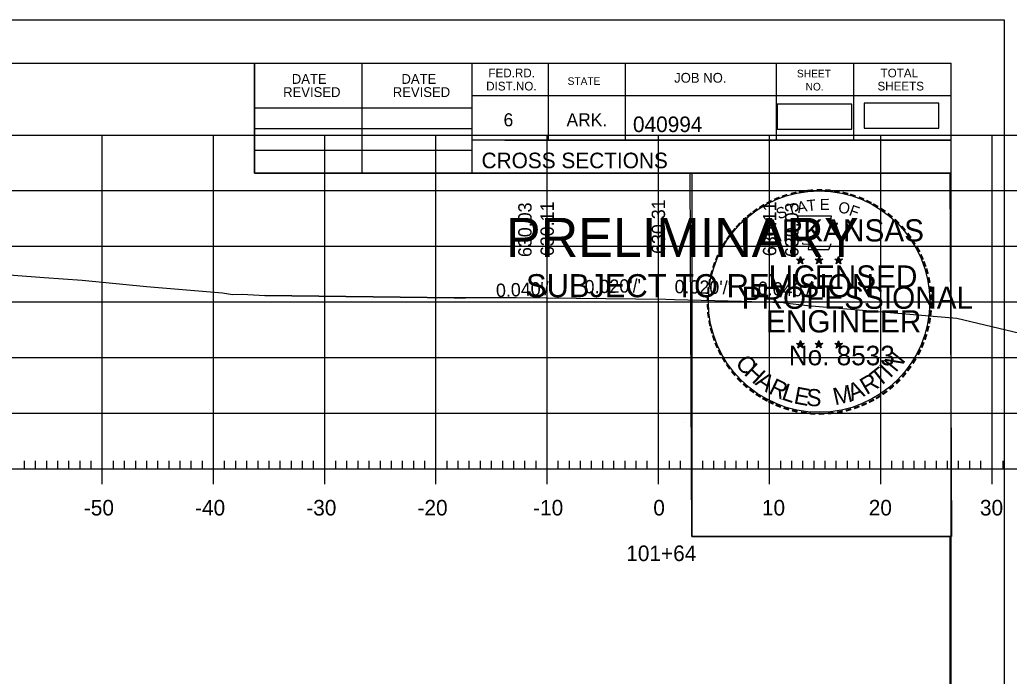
# Model space of a CAD drawing. Extents: x 1381471 to 1382703, y 370300 to 371487.
# Drawn here: x 1382079.2 to 1382168.2, y 370488.6 to 370547.6 of the extents above; entities that cross this region are included whole.
import ezdxf

# ---------------------------------------------------------------- set-up
doc = ezdxf.new("R2010")
doc.units = 0
for name, color, linetype in [('Level 26', 7, 'Continuous'), ('Level 45', 7, 'Continuous'), ('Level 6', 7, 'Continuous'), ('Level 8', 7, 'Continuous'), ('Level 9', 7, 'Continuous')]:
    doc.layers.add(name, color=color, linetype=linetype)

msp = doc.modelspace()

# ---------------------------------------------------------------- linework, layer by layer
at = {"layer": 'Level 26'}
for p, q in [((1381834.371, 370547.628), (1382167.705, 370547.628)), ((1382138.986, 370511.397), (1382138.986, 370511.397))]:
    msp.add_line(p, q, dxfattribs=at)
for points in [[(1381834.365, 370547.628), (1382167.705, 370547.628), (1382167.705, 370334.29), (1381834.365, 370334.29)], [(1382080.692, 370543.733), (1382100.312, 370543.733), (1382100.312, 370533.853), (1382116.424, 370533.853), (1382139.624, 370533.853), (1382139.624, 370501.183), (1382162.831, 370501.183), (1382162.952, 370338.273), (1381846.772, 370338.273), (1381846.772, 370543.733)], [(1382139.484, 370533.853), (1382162.831, 370533.853), (1382162.972, 370501.183), (1382139.624, 370501.183)]]:
    msp.add_lwpolyline(points, close=True, dxfattribs=at)
msp.add_circle((1382151.064, 370522.293), 9.952, dxfattribs=at)
at = {"layer": 'Level 45'}
for p, q in [((1381996.613, 370537.267), (1382276.613, 370537.267)), ((1382086.613, 370507.267), (1382086.613, 370537.267)), ((1382096.613, 370507.267), (1382096.613, 370537.267)), ((1382106.613, 370507.267), (1382106.613, 370537.267)), ((1382116.613, 370507.267), (1382116.613, 370537.267)), ((1382126.613, 370507.267), (1382126.613, 370537.267)), ((1382136.613, 370507.267), (1382136.613, 370537.267)), ((1382146.613, 370507.267), (1382146.613, 370537.267)), ((1382156.613, 370507.267), (1382156.613, 370537.267)), ((1382166.613, 370507.267), (1382166.613, 370537.267)), ((1381996.613, 370532.267), (1382276.613, 370532.267)), ((1381996.613, 370527.267), (1382276.613, 370527.267)), ((1381996.613, 370522.267), (1382276.613, 370522.267)), ((1382118.241, 370522.631), (1382101.218, 370522.852)), ((1381996.613, 370517.267), (1382276.613, 370517.267)), ((1381996.613, 370512.267), (1382276.613, 370512.267)), ((1382086.613, 370505.867), (1382086.613, 370508.667)), ((1382096.613, 370505.867), (1382096.613, 370508.667)), ((1382106.613, 370505.867), (1382106.613, 370508.667)), ((1382116.613, 370505.867), (1382116.613, 370508.667)), ((1382126.613, 370505.867), (1382126.613, 370508.667)), ((1382136.613, 370505.867), (1382136.613, 370508.667)), ((1382146.613, 370505.867), (1382146.613, 370508.667)), ((1382156.613, 370505.867), (1382156.613, 370508.667)), ((1382166.613, 370505.867), (1382166.613, 370508.667)), ((1381996.613, 370507.267), (1382276.613, 370507.267)), ((1381996.613, 370507.267), (1382276.613, 370507.267)), ((1382079.613, 370507.267), (1382079.613, 370507.967)), ((1382080.613, 370507.267), (1382080.613, 370507.967)), ((1382081.613, 370507.267), (1382081.613, 370507.967)), ((1382082.613, 370507.267), (1382082.613, 370507.967)), ((1382083.613, 370507.267), (1382083.613, 370507.967)), ((1382084.613, 370507.267), (1382084.613, 370507.967)), ((1382085.613, 370507.267), (1382085.613, 370507.967)), ((1382087.613, 370507.267), (1382087.613, 370507.967)), ((1382088.613, 370507.267), (1382088.613, 370507.967)), ((1382089.613, 370507.267), (1382089.613, 370507.967)), ((1382090.613, 370507.267), (1382090.613, 370507.967)), ((1382091.613, 370507.267), (1382091.613, 370507.967)), ((1382092.613, 370507.267), (1382092.613, 370507.967)), ((1382093.613, 370507.267), (1382093.613, 370507.967)), ((1382094.613, 370507.267), (1382094.613, 370507.967)), ((1382095.613, 370507.267), (1382095.613, 370507.967)), ((1382097.613, 370507.267), (1382097.613, 370507.967)), ((1382098.613, 370507.267), (1382098.613, 370507.967)), ((1382099.613, 370507.267), (1382099.613, 370507.967)), ((1382100.613, 370507.267), (1382100.613, 370507.967)), ((1382101.613, 370507.267), (1382101.613, 370507.967)), ((1382102.613, 370507.267), (1382102.613, 370507.967)), ((1382103.613, 370507.267), (1382103.613, 370507.967)), ((1382104.613, 370507.267), (1382104.613, 370507.967)), ((1382105.613, 370507.267), (1382105.613, 370507.967)), ((1382107.613, 370507.267), (1382107.613, 370507.967)), ((1382108.613, 370507.267), (1382108.613, 370507.967)), ((1382109.613, 370507.267), (1382109.613, 370507.967)), ((1382110.613, 370507.267), (1382110.613, 370507.967)), ((1382111.613, 370507.267), (1382111.613, 370507.967)), ((1382112.613, 370507.267), (1382112.613, 370507.967)), ((1382113.613, 370507.267), (1382113.613, 370507.967)), ((1382114.613, 370507.267), (1382114.613, 370507.967)), ((1382115.613, 370507.267), (1382115.613, 370507.967)), ((1382117.613, 370507.267), (1382117.613, 370507.967)), ((1382118.613, 370507.267), (1382118.613, 370507.967)), ((1382119.613, 370507.267), (1382119.613, 370507.967)), ((1382120.613, 370507.267), (1382120.613, 370507.967)), ((1382121.613, 370507.267), (1382121.613, 370507.967)), ((1382122.613, 370507.267), (1382122.613, 370507.967)), ((1382123.613, 370507.267), (1382123.613, 370507.967)), ((1382124.613, 370507.267), (1382124.613, 370507.967)), ((1382125.613, 370507.267), (1382125.613, 370507.967)), ((1382127.613, 370507.267), (1382127.613, 370507.967)), ((1382128.613, 370507.267), (1382128.613, 370507.967)), ((1382129.613, 370507.267), (1382129.613, 370507.967)), ((1382130.613, 370507.267), (1382130.613, 370507.967)), ((1382131.613, 370507.267), (1382131.613, 370507.967)), ((1382132.613, 370507.267), (1382132.613, 370507.967)), ((1382133.613, 370507.267), (1382133.613, 370507.967)), ((1382134.613, 370507.267), (1382134.613, 370507.967)), ((1382135.613, 370507.267), (1382135.613, 370507.967)), ((1382137.613, 370507.267), (1382137.613, 370507.967)), ((1382138.613, 370507.267), (1382138.613, 370507.967)), ((1382139.613, 370507.267), (1382139.613, 370507.967)), ((1382140.613, 370507.267), (1382140.613, 370507.967)), ((1382141.613, 370507.267), (1382141.613, 370507.967)), ((1382142.613, 370507.267), (1382142.613, 370507.967)), ((1382143.613, 370507.267), (1382143.613, 370507.967)), ((1382144.613, 370507.267), (1382144.613, 370507.967)), ((1382145.613, 370507.267), (1382145.613, 370507.967)), ((1382147.613, 370507.267), (1382147.613, 370507.967)), ((1382148.613, 370507.267), (1382148.613, 370507.967)), ((1382149.613, 370507.267), (1382149.613, 370507.967)), ((1382150.613, 370507.267), (1382150.613, 370507.967)), ((1382151.613, 370507.267), (1382151.613, 370507.967)), ((1382152.613, 370507.267), (1382152.613, 370507.967)), ((1382153.613, 370507.267), (1382153.613, 370507.967)), ((1382154.613, 370507.267), (1382154.613, 370507.967)), ((1382155.613, 370507.267), (1382155.613, 370507.967)), ((1382157.613, 370507.267), (1382157.613, 370507.967)), ((1382158.613, 370507.267), (1382158.613, 370507.967)), ((1382159.613, 370507.267), (1382159.613, 370507.967)), ((1382160.613, 370507.267), (1382160.613, 370507.967)), ((1382161.613, 370507.267), (1382161.613, 370507.967)), ((1382162.613, 370507.267), (1382162.613, 370507.967)), ((1382163.613, 370507.267), (1382163.613, 370507.967)), ((1382164.613, 370507.267), (1382164.613, 370507.967)), ((1382165.613, 370507.267), (1382165.613, 370507.967)), ((1382167.613, 370507.267), (1382167.613, 370507.967))]:
    msp.add_line(p, q, dxfattribs=at)
for points in [[(1382070.712, 370525.284), (1382081.391, 370524.455), (1382084.791, 370524.226), (1382090.588, 370523.658), (1382097.41, 370523.091), (1382098.331, 370522.938), (1382099.201, 370522.951), (1382101.218, 370522.852), (1382118.241, 370522.631), (1382118.948, 370522.63), (1382119.266, 370522.623), (1382123.374, 370522.676), (1382123.825, 370522.668), (1382137.286, 370522.508), (1382138.076, 370522.487), (1382144.074, 370522.318), (1382147.845, 370522.211), (1382147.877, 370522.205), (1382147.953, 370522.197), (1382150.033, 370521.941), (1382163.451, 370520.799), (1382171.626, 370518.866)], [(1382123.825, 370522.668), (1382119.266, 370522.623), (1382118.241, 370522.631)]]:
    msp.add_lwpolyline(points, dxfattribs=at)
at = {"layer": 'Level 6'}
for p, q in [((1381846.772, 370543.733), (1382162.952, 370543.733)), ((1382100.312, 370533.853), (1382100.312, 370543.733)), ((1382109.992, 370533.853), (1382109.992, 370543.733)), ((1382119.852, 370543.733), (1382119.852, 370533.853)), ((1382126.692, 370543.733), (1382126.692, 370536.793)), ((1382133.632, 370543.733), (1382133.632, 370536.793)), ((1382147.212, 370543.733), (1382147.212, 370536.793)), ((1382154.152, 370543.733), (1382154.152, 370536.793)), ((1382162.952, 370338.273), (1382162.952, 370543.733)), ((1382162.952, 370540.793), (1382119.852, 370540.793)), ((1382162.952, 370540.813), (1382162.952, 370540.813)), ((1382100.312, 370539.713), (1382119.852, 370539.713)), ((1382100.312, 370537.853), (1382119.852, 370537.853)), ((1382162.952, 370536.793), (1382119.852, 370536.793)), ((1382122.812, 370536.793), (1382162.952, 370536.793)), ((1382100.312, 370535.913), (1382119.852, 370535.913)), ((1382162.952, 370533.853), (1382100.312, 370533.853))]:
    msp.add_line(p, q, dxfattribs=at)
for points in [[(1382147.299, 370537.804), (1382154.01, 370537.804), (1382154.01, 370540.041), (1382147.299, 370540.041)], [(1382155.106, 370537.896), (1382161.817, 370537.896), (1382161.817, 370540.133), (1382155.106, 370540.133)]]:
    msp.add_lwpolyline(points, close=True, dxfattribs=at)
at = {"layer": 'Level 8'}
for p, q in [((1382149.037, 370526.108), (1382149.386, 370525.997)), ((1382149.037, 370526.108), (1382149.29, 370526.063)), ((1382149.037, 370526.108), (1382149.274, 370525.986)), ((1382149.17, 370525.7), (1382149.386, 370525.997)), ((1382149.17, 370525.7), (1382149.296, 370525.944)), ((1382149.17, 370525.7), (1382149.384, 370525.917)), ((1382149.386, 370526.362), (1382149.345, 370526.11)), ((1382149.599, 370525.7), (1382149.384, 370525.914)), ((1382149.386, 370525.997), (1382149.386, 370526.362)), ((1382149.386, 370526.362), (1382149.435, 370526.112)), ((1382149.733, 370526.108), (1382149.386, 370525.997)), ((1382149.599, 370525.7), (1382149.386, 370525.997)), ((1382149.733, 370526.108), (1382149.447, 370526.059)), ((1382149.599, 370525.7), (1382149.462, 370525.991)), ((1382149.733, 370526.108), (1382149.529, 370526.006)), ((1382150.707, 370526.108), (1382151.056, 370525.997)), ((1382150.707, 370526.108), (1382150.96, 370526.063)), ((1382150.707, 370526.108), (1382150.944, 370525.986)), ((1382150.84, 370525.7), (1382151.056, 370525.997)), ((1382150.84, 370525.7), (1382150.966, 370525.944)), ((1382150.84, 370525.7), (1382151.054, 370525.917)), ((1382151.056, 370526.362), (1382151.015, 370526.11)), ((1382151.269, 370525.7), (1382151.054, 370525.914)), ((1382151.056, 370525.997), (1382151.056, 370526.362)), ((1382151.056, 370526.362), (1382151.105, 370526.112)), ((1382151.403, 370526.108), (1382151.056, 370525.997)), ((1382151.269, 370525.7), (1382151.056, 370525.997)), ((1382151.403, 370526.108), (1382151.117, 370526.059)), ((1382151.269, 370525.7), (1382151.132, 370525.991)), ((1382151.403, 370526.108), (1382151.199, 370526.006)), ((1382152.471, 370526.096), (1382152.82, 370525.985)), ((1382152.471, 370526.096), (1382152.724, 370526.051)), ((1382152.471, 370526.096), (1382152.708, 370525.974)), ((1382152.604, 370525.688), (1382152.82, 370525.985)), ((1382152.604, 370525.688), (1382152.73, 370525.932)), ((1382152.604, 370525.688), (1382152.818, 370525.905)), ((1382152.82, 370526.35), (1382152.779, 370526.098)), ((1382153.033, 370525.688), (1382152.818, 370525.902)), ((1382152.82, 370525.985), (1382152.82, 370526.35)), ((1382152.82, 370526.35), (1382152.869, 370526.1)), ((1382153.167, 370526.096), (1382152.82, 370525.985)), ((1382153.033, 370525.688), (1382152.82, 370525.985)), ((1382153.167, 370526.096), (1382152.881, 370526.047)), ((1382153.033, 370525.688), (1382152.896, 370525.979)), ((1382153.167, 370526.096), (1382152.963, 370525.994)), ((1382149.382, 370518.789), (1382149.341, 370518.537)), ((1382149.382, 370518.424), (1382149.382, 370518.789)), ((1382149.382, 370518.789), (1382149.431, 370518.539)), ((1382151.051, 370518.789), (1382151.01, 370518.537)), ((1382151.051, 370518.424), (1382151.051, 370518.789)), ((1382151.051, 370518.789), (1382151.1, 370518.539)), ((1382152.818, 370518.779), (1382152.777, 370518.527)), ((1382152.818, 370518.414), (1382152.818, 370518.779)), ((1382152.818, 370518.779), (1382152.867, 370518.529)), ((1382149.033, 370518.535), (1382149.382, 370518.424)), ((1382149.033, 370518.535), (1382149.286, 370518.49)), ((1382149.033, 370518.535), (1382149.27, 370518.413)), ((1382149.166, 370518.127), (1382149.382, 370518.424)), ((1382149.166, 370518.127), (1382149.292, 370518.371)), ((1382149.166, 370518.127), (1382149.38, 370518.344)), ((1382149.595, 370518.127), (1382149.38, 370518.341)), ((1382149.729, 370518.535), (1382149.382, 370518.424)), ((1382149.595, 370518.127), (1382149.382, 370518.424)), ((1382149.729, 370518.535), (1382149.443, 370518.486)), ((1382149.595, 370518.127), (1382149.458, 370518.418)), ((1382149.729, 370518.535), (1382149.525, 370518.433)), ((1382150.702, 370518.535), (1382151.051, 370518.424)), ((1382150.702, 370518.535), (1382150.955, 370518.49)), ((1382150.702, 370518.535), (1382150.939, 370518.413)), ((1382150.835, 370518.127), (1382151.051, 370518.424)), ((1382150.835, 370518.127), (1382150.961, 370518.371)), ((1382150.835, 370518.127), (1382151.049, 370518.344)), ((1382151.264, 370518.127), (1382151.049, 370518.341)), ((1382151.398, 370518.535), (1382151.051, 370518.424)), ((1382151.264, 370518.127), (1382151.051, 370518.424)), ((1382151.398, 370518.535), (1382151.112, 370518.486)), ((1382151.264, 370518.127), (1382151.127, 370518.418)), ((1382151.398, 370518.535), (1382151.194, 370518.433)), ((1382152.469, 370518.525), (1382152.818, 370518.414)), ((1382152.469, 370518.525), (1382152.722, 370518.48)), ((1382152.469, 370518.525), (1382152.706, 370518.403)), ((1382152.602, 370518.117), (1382152.818, 370518.414)), ((1382152.602, 370518.117), (1382152.728, 370518.361)), ((1382152.602, 370518.117), (1382152.816, 370518.334)), ((1382153.031, 370518.117), (1382152.816, 370518.331)), ((1382153.165, 370518.525), (1382152.818, 370518.414)), ((1382153.031, 370518.117), (1382152.818, 370518.414)), ((1382153.165, 370518.525), (1382152.879, 370518.476)), ((1382153.031, 370518.117), (1382152.894, 370518.408)), ((1382153.165, 370518.525), (1382152.961, 370518.423))]:
    msp.add_line(p, q, dxfattribs=at)
for points in [[(1382149.078, 370529.986), (1382149.347, 370529.159)], [(1382152.589, 370529.064), (1382152.731, 370529.348), (1382152.046, 370529.324), (1382152.194, 370529.986), (1382149.078, 370529.986)], [(1382149.57, 370527.563), (1382149.57, 370527.476), (1382150.133, 370527.457), (1382150.079, 370526.984), (1382151.949, 370526.984), (1382152.15, 370527.52)], [(1382149.386, 370526.362), (1382149.599, 370525.7), (1382149.037, 370526.108), (1382149.733, 370526.108), (1382149.17, 370525.7), (1382149.386, 370526.362)], [(1382151.056, 370526.362), (1382151.269, 370525.7), (1382150.707, 370526.108), (1382151.403, 370526.108), (1382150.84, 370525.7), (1382151.056, 370526.362)], [(1382152.82, 370526.35), (1382153.033, 370525.688), (1382152.471, 370526.096), (1382153.167, 370526.096), (1382152.604, 370525.688), (1382152.82, 370526.35)], [(1382149.382, 370518.789), (1382149.595, 370518.127), (1382149.033, 370518.535), (1382149.729, 370518.535), (1382149.166, 370518.127), (1382149.382, 370518.789)], [(1382151.051, 370518.789), (1382151.264, 370518.127), (1382150.702, 370518.535), (1382151.398, 370518.535), (1382150.835, 370518.127), (1382151.051, 370518.789)], [(1382152.818, 370518.779), (1382153.031, 370518.117), (1382152.469, 370518.525), (1382153.165, 370518.525), (1382152.602, 370518.117), (1382152.818, 370518.779)]]:
    msp.add_lwpolyline(points, dxfattribs=at)
for centre, radius in [((1382149.385, 370525.996), 0.172), ((1382149.385, 370525.996), 0.145), ((1382149.385, 370525.996), 0.116), ((1382149.385, 370525.996), 0.0991), ((1382149.385, 370525.996), 0.0747), ((1382149.385, 370525.996), 0.0495), ((1382149.385, 370525.996), 0.0296), ((1382151.055, 370525.996), 0.172), ((1382151.055, 370525.996), 0.145), ((1382151.055, 370525.996), 0.116), ((1382151.055, 370525.996), 0.0991), ((1382151.055, 370525.996), 0.0747), ((1382151.055, 370525.996), 0.0495), ((1382151.055, 370525.996), 0.0296), ((1382152.819, 370525.984), 0.172), ((1382152.819, 370525.984), 0.145), ((1382152.819, 370525.984), 0.116), ((1382152.819, 370525.984), 0.0991), ((1382152.819, 370525.984), 0.0747), ((1382152.819, 370525.984), 0.0495), ((1382152.819, 370525.984), 0.0296), ((1382149.381, 370518.423), 0.172), ((1382149.381, 370518.423), 0.145), ((1382149.381, 370518.423), 0.116), ((1382149.381, 370518.423), 0.0991), ((1382149.381, 370518.423), 0.0747), ((1382149.381, 370518.423), 0.0495), ((1382149.381, 370518.423), 0.0296), ((1382151.05, 370518.423), 0.172), ((1382151.05, 370518.423), 0.145), ((1382151.05, 370518.423), 0.116), ((1382151.05, 370518.423), 0.0991), ((1382151.05, 370518.423), 0.0747), ((1382151.05, 370518.423), 0.0495), ((1382151.05, 370518.423), 0.0296), ((1382152.817, 370518.413), 0.172), ((1382152.817, 370518.413), 0.145), ((1382152.817, 370518.413), 0.116), ((1382152.817, 370518.413), 0.0991), ((1382152.817, 370518.413), 0.0747), ((1382152.817, 370518.413), 0.0495), ((1382152.817, 370518.413), 0.0296)]:
    msp.add_circle(centre, radius, dxfattribs=at)

# ---------------------------------------------------------------- texts
at = {"layer": 'Level 45'}
for s, rotation, p in [('630.03', 90, (1382125.213, 370526.297)), ('630.11', 90, (1382127.213, 370526.377)), ('630.31', 90, (1382137.213, 370526.577)), ('630.11', 90, (1382147.213, 370526.377)), ('630.03', 90, (1382149.213, 370526.297)), ("0.040'/'", 2.29061, (1382122.034, 370522.694)), ("0.020'/'", 1.14576, (1382129.989, 370523.027)), ("0.020'/'", 358.85424, (1382138.062, 370523.048)), ("0.040'/'", 357.70939, (1382145.536, 370522.909))]:
    msp.add_text(s, height=1.2, rotation=rotation, dxfattribs=at).set_placement(p)
for s, p in [('-50', (1382084.954, 370503.067)), ('-40', (1382094.954, 370503.067)), ('-30', (1382104.954, 370503.067)), ('-20', (1382114.954, 370503.067)), ('-10', (1382125.351, 370503.067)), ('0', (1382136.156, 370503.067)), ('10', (1382145.924, 370503.067)), ('20', (1382155.528, 370503.067)), ('30', (1382165.528, 370503.067)), ('101+64', (1382133.725, 370498.967))]:
    msp.add_text(s, height=1.4, dxfattribs=at).set_placement(p)
at = {"layer": 'Level 6'}
for s, height, p in [('DATE', 0.8792, (1382103.65, 370541.869)), ('DATE', 0.8792, (1382113.51, 370541.869)), ('FED.RD.', 0.7819, (1382121.332, 370542.453)), ('JOB NO.', 0.8792, (1382138.032, 370541.973)), ('SHEET', 0.684, (1382149.072, 370542.453)), ('TOTAL', 0.7819, (1382156.592, 370542.453)), ('DIST.NO.', 0.7819, (1382121.132, 370541.273)), ('STATE', 0.684, (1382128.452, 370541.773)), ('NO.', 0.684, (1382149.852, 370541.273)), ('SHEETS', 0.7819, (1382156.312, 370541.273)), ('REVISED', 0.8792, (1382102.87, 370540.689)), ('REVISED', 0.8792, (1382112.73, 370540.689)), ('6', 1.172, (1382122.692, 370538.053)), ('ARK.', 1.1723, (1382128.352, 370538.053)), ('040994', 1.4, (1382134.328, 370537.532)), ('CROSS SECTIONS', 1.4, (1382120.716, 370534.283))]:
    msp.add_text(s, height=height, rotation=360, dxfattribs=at).set_placement(p)
at = {"layer": 'Level 8'}
for s, height, rotation, p in [('-', 1.6, 13.63015, (1382148.576, 370531.354)), ('-', 1.6, 10.21935, (1382149.254, 370531.516)), ('-', 1.6, 5.89682, (1382149.983, 370531.626)), ('-', 1.6, 0.18623, (1382150.755, 370531.698)), ('-', 1.6, 357.74304, (1382151.478, 370531.685)), ('-', 1.6, 352.16172, (1382152.222, 370531.629)), ('-', 1.6, 347.20489, (1382152.941, 370531.515)), ('-', 1.6, 342.3362, (1382153.576, 370531.36)), ('-', 1.6, 28.79182, (1382146.559, 370530.527)), ('-', 1.6, 24.30721, (1382147.192, 370530.844)), ('-', 1.6, 19.17608, (1382147.826, 370531.113)), ('T', 1, 16.4036, (1382148.347, 370529.995)), ('A', 1, 11.21318, (1382149.173, 370530.246)), ('T', 1, 6.02276, (1382150.022, 370530.412)), ('E', 1, 0.83234, (1382151.127, 370530.522)), ('O', 1, 350.4515, (1382152.731, 370530.312)), ('-', 1.6, 337.85509, (1382154.311, 370531.137)), ('-', 1.6, 334.12109, (1382154.942, 370530.866)), ('-', 1.6, 329.64089, (1382155.521, 370530.583)), ('-', 1.6, 38.95066, (1382144.908, 370529.384)), ('-', 1.6, 36.23174, (1382145.384, 370529.762)), ('-', 1.6, 34.06357, (1382145.962, 370530.157)), ('S', 1, 21.59401, (1382147.433, 370529.664)), ('F', 1, 340.07066, (1382153.685, 370530.084)), ('-', 1.6, 325.86266, (1382156.164, 370530.222)), ('-', 1.6, 320.52971, (1382156.774, 370529.796)), ('-', 1.6, 48.42305, (1382144.027, 370528.489)), ('-', 1.6, 42.96224, (1382144.475, 370528.967)), ('ARKANSAS', 2, 360, (1382145.931, 370527.698)), ('-', 1.6, 315.57859, (1382157.373, 370529.308)), ('-', 1.6, 50.61417, (1382143.624, 370528.003)), ('-', 1.6, 309.87973, (1382157.942, 370528.758)), ('-', 1.6, 306.65218, (1382158.467, 370528.156)), ('-', 1.6, 58.07063, (1382142.886, 370526.909)), ('-', 1.6, 54.23247, (1382143.211, 370527.436)), ('-', 1.4, 303.67529, (1382158.953, 370527.588)), ('-', 1.6, 62.87135, (1382142.573, 370526.295)), ('-', 1.6, 299.66835, (1382159.272, 370526.981)), ('-', 1.6, 72.39447, (1382142.095, 370525.054)), ('-', 1.6, 67.77427, (1382142.314, 370525.684)), ('DWB', 0.01, 360, (1382149.373, 370525.992)), ('DWB', 0.01, 360, (1382151.043, 370525.992)), ('DWB', 0.01, 360, (1382152.807, 370525.981)), ('-', 1.6, 294.66279, (1382159.596, 370526.369)), ('-', 1.6, 290.57283, (1382159.853, 370525.792)), ('-', 1.6, 75.46096, (1382141.898, 370524.34)), ('LICENSED', 2, 360, (1382146.528, 370523.549)), ('-', 1.6, 285.12326, (1382160.087, 370525.212)), ('-', 1.6, 81.20126, (1382141.766, 370523.627)), ('-', 1.6, 280.54934, (1382160.287, 370524.47)), ('-', 1.6, 85.18634, (1382141.69, 370522.936)), ('PROFESSIONAL', 2, 360, (1382144.105, 370521.645)), ('-', 1.6, 276.59616, (1382160.449, 370523.702)), ('-', 1.6, 89.06224, (1382141.665, 370522.235)), ('-', 1.6, 274.33011, (1382160.509, 370522.98)), ('-', 1.6, 269.94067, (1382160.543, 370522.348)), ('-', 1.6, 94.19588, (1382141.7, 370521.51)), ('-', 1.6, 98.94793, (1382141.772, 370520.843)), ('ENGINEER', 2, 360, (1382146.292, 370519.52)), ('-', 1.6, 263.5172, (1382160.524, 370521.682)), ('-', 1.6, 101.71495, (1382141.907, 370520.11)), ('-', 1.6, 260.99529, (1382160.453, 370521.028)), ('-', 1.6, 105.45785, (1382142.069, 370519.515)), ('-', 1.6, 255.7626, (1382160.343, 370520.35)), ('-', 1.6, 109.08742, (1382142.284, 370518.884)), ('-', 1.6, 247.88866, (1382159.939, 370518.957)), ('-', 1.6, 252.86809, (1382160.162, 370519.63)), ('-', 1.6, 114.06432, (1382142.538, 370518.288)), ('-', 1.6, 115.72885, (1382142.843, 370517.67)), ('No. 8533', 1.757, 360, (1382148.334, 370516.569)), ('DWB', 0.01, 360, (1382149.369, 370518.419)), ('DWB', 0.01, 360, (1382151.038, 370518.419)), ('DWB', 0.01, 360, (1382152.805, 370518.409)), ('N', 1.54, 50.78344, (1382157.971, 370515.868)), ('-', 1.6, 244.61971, (1382159.677, 370518.328)), ('-', 1.6, 120.44712, (1382143.2, 370517.084)), ('C', 1.54, 309.95483, (1382143.456, 370516.716)), ('-', 1.6, 239.07125, (1382159.283, 370517.576)), ('-', 1.6, 125.89344, (1382143.603, 370516.523)), ('-', 1.6, 130.71812, (1382144.065, 370515.971)), ('H', 1.54, 317.38726, (1382144.242, 370515.778)), ('T', 1.54, 38.42805, (1382156.437, 370514.539)), ('I', 1.54, 46.30332, (1382157.448, 370515.348)), ('-', 1.6, 233.84524, (1382158.881, 370516.923)), ('-', 1.6, 134.22381, (1382144.582, 370515.426)), ('A', 1.54, 325.55777, (1382145.237, 370514.875)), ('R', 1.54, 334.31873, (1382146.435, 370514.074)), ('R', 1.54, 30.55277, (1382155.324, 370513.876)), ('-', 1.6, 225.76533, (1382157.972, 370515.793)), ('-', 1.6, 231.25377, (1382158.451, 370516.357)), ('-', 1.6, 138.93382, (1382145.107, 370514.962)), ('-', 1.6, 144.64634, (1382145.663, 370514.556)), ('L', 1.54, 342.19401, (1382147.604, 370513.517)), ('E', 1.54, 349.33121, (1382148.722, 370513.155)), ('S', 1.54, 356.46841, (1382149.875, 370512.935)), ('M', 1.54, 12.44038, (1382152.496, 370512.969)), ('A', 1.54, 21.7918, (1382153.992, 370513.325)), ('-', 1.6, 215.73633, (1382156.901, 370514.812)), ('-', 1.6, 221.08509, (1382157.45, 370515.284)), ('-', 1.6, 148.08978, (1382146.224, 370514.185)), ('-', 1.6, 151.57039, (1382146.803, 370513.86)), ('-', 1.6, 154.60019, (1382147.325, 370513.613)), ('-', 1.6, 207.35684, (1382155.809, 370514.079)), ('-', 1.6, 212.24909, (1382156.367, 370514.425)), ('-', 1.6, 158.56121, (1382147.949, 370513.359)), ('-', 1.6, 162.79826, (1382148.636, 370513.146)), ('-', 1.6, 167.55551, (1382149.351, 370512.982)), ('-', 1.6, 191.28576, (1382153.16, 370513.046)), ('-', 1.6, 195.47429, (1382153.889, 370513.245)), ('-', 1.6, 200.71842, (1382154.566, 370513.487)), ('-', 1.6, 204.25161, (1382155.185, 370513.76)), ('-', 1.6, 173.11546, (1382150.123, 370512.872)), ('-', 1.6, 176.51827, (1382150.871, 370512.819)), ('-', 1.6, 181.59176, (1382151.615, 370512.838)), ('-', 1.6, 185.81666, (1382152.424, 370512.914))]:
    msp.add_text(s, height=height, rotation=rotation, dxfattribs=at).set_placement(p)
at = {"layer": 'Level 9'}
for s, height, p in [('PRELIMINARY', 3.5, (1382122.903, 370526.316)), ('DWB', 0.01, (1382123.65, 370528.165)), ('SUBJECT TO REVISION', 2.07511, (1382124.712, 370522.687))]:
    msp.add_text(s, height=height, rotation=360, dxfattribs=at).set_placement(p)

doc.saveas('drawing.dxf')
